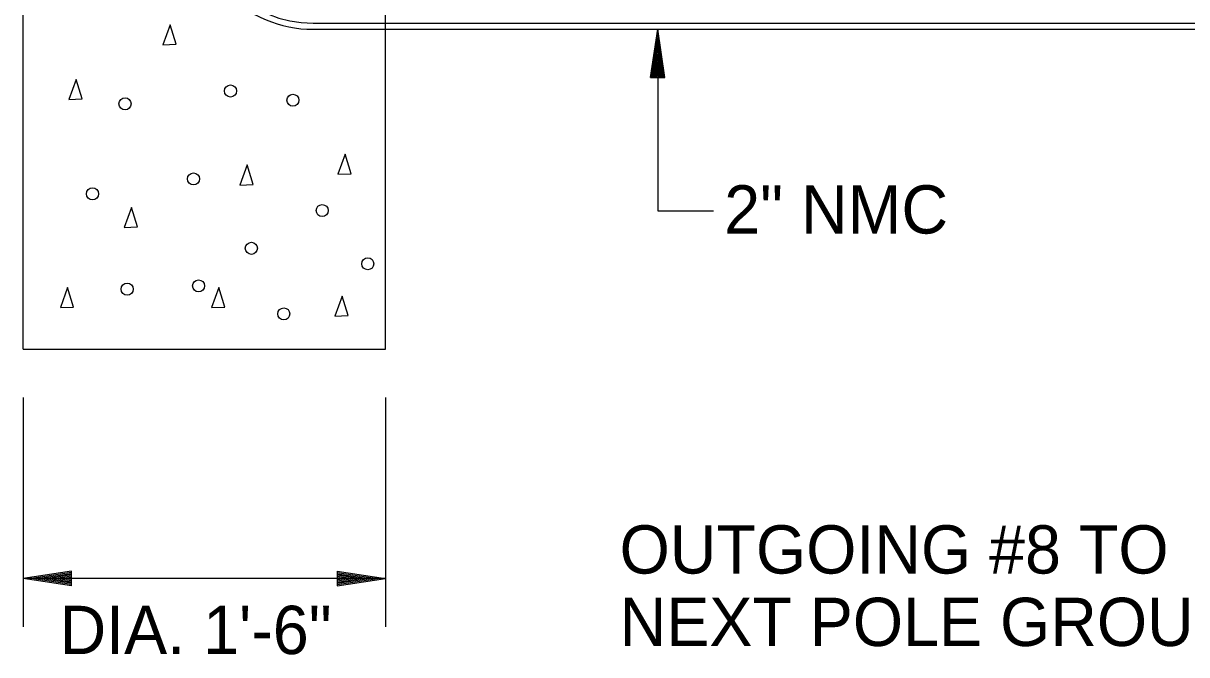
# Model space of a CAD drawing. Extents: x 1695551 to 1695718, y 544410 to 544516.
# Drawn here: x 1695569.87 to 1695587.94, y 544471.5 to 544481.31 of the extents above; entities that cross this region are included whole.
import ezdxf

# ---------------------------------------------------------------- set-up
doc = ezdxf.new("R2010")
doc.units = 0
doc.layers.add('R_Draft', color=7, linetype='Continuous')

msp = doc.modelspace()

# ---------------------------------------------------------------- linework, layer by layer
at = {"layer": 'R_Draft'}
for p, q in [((1695569.874, 544476.251), (1695569.874, 544487.501)), ((1695575.499, 544476.251), (1695575.499, 544487.501)), ((1695574.374, 544481.311), (1695592.925, 544481.311)), ((1695574.374, 544481.217), (1695592.925, 544481.217)), ((1695579.615, 544480.467), (1695579.727, 544481.217)), ((1695579.727, 544481.217), (1695579.727, 544478.399)), ((1695579.84, 544480.467), (1695579.727, 544481.217)), ((1695579.633, 544480.467), (1695579.727, 544481.092)), ((1695579.821, 544480.467), (1695579.727, 544481.092)), ((1695579.653, 544480.467), (1695579.727, 544480.963)), ((1695579.671, 544480.467), (1695579.727, 544480.838)), ((1695579.802, 544480.467), (1695579.727, 544480.963)), ((1695579.783, 544480.467), (1695579.727, 544480.838)), ((1695579.691, 544480.467), (1695579.727, 544480.711)), ((1695579.764, 544480.467), (1695579.727, 544480.711)), ((1695579.615, 544480.467), (1695579.84, 544480.467)), ((1695579.71, 544480.467), (1695579.727, 544480.585)), ((1695579.745, 544480.467), (1695579.727, 544480.585)), ((1695579.727, 544478.399), (1695580.591, 544478.399)), ((1695569.874, 544476.251), (1695575.499, 544476.251)), ((1695569.874, 544475.501), (1695569.874, 544471.939)), ((1695575.499, 544475.501), (1695575.499, 544471.939)), ((1695570.624, 544472.801), (1695569.874, 544472.689)), ((1695575.499, 544472.689), (1695569.874, 544472.689)), ((1695570.624, 544472.576), (1695569.874, 544472.689)), ((1695570.624, 544472.783), (1695569.999, 544472.689)), ((1695570.624, 544472.595), (1695569.999, 544472.689)), ((1695570.624, 544472.763), (1695570.128, 544472.689)), ((1695570.624, 544472.614), (1695570.128, 544472.689)), ((1695570.624, 544472.745), (1695570.253, 544472.689)), ((1695570.624, 544472.633), (1695570.253, 544472.689)), ((1695570.624, 544472.726), (1695570.38, 544472.689)), ((1695570.624, 544472.652), (1695570.38, 544472.689)), ((1695570.624, 544472.706), (1695570.505, 544472.689)), ((1695570.624, 544472.671), (1695570.505, 544472.689)), ((1695570.624, 544472.576), (1695570.624, 544472.801)), ((1695574.749, 544472.801), (1695575.499, 544472.689)), ((1695574.749, 544472.801), (1695574.749, 544472.576)), ((1695574.749, 544472.783), (1695575.373, 544472.689)), ((1695574.749, 544472.763), (1695575.244, 544472.689)), ((1695574.749, 544472.745), (1695575.12, 544472.689)), ((1695574.749, 544472.725), (1695574.992, 544472.689)), ((1695574.749, 544472.706), (1695574.867, 544472.689)), ((1695574.749, 544472.576), (1695575.499, 544472.689)), ((1695574.749, 544472.652), (1695574.992, 544472.689)), ((1695574.749, 544472.614), (1695575.244, 544472.689)), ((1695574.749, 544472.595), (1695575.373, 544472.689)), ((1695574.749, 544472.633), (1695575.12, 544472.689)), ((1695574.749, 544472.671), (1695574.867, 544472.689))]:
    msp.add_line(p, q, dxfattribs=at)
for points in [[(1695572.156, 544481.287), (1695572.043, 544480.975), (1695572.249, 544480.984), (1695572.156, 544481.287)], [(1695570.695, 544480.44), (1695570.582, 544480.129), (1695570.788, 544480.137), (1695570.695, 544480.44)], [(1695574.873, 544479.278), (1695574.76, 544478.967), (1695574.966, 544478.975), (1695574.873, 544479.278)], [(1695573.353, 544479.111), (1695573.239, 544478.799), (1695573.445, 544478.808), (1695573.353, 544479.111)], [(1695571.557, 544478.452), (1695571.443, 544478.141), (1695571.65, 544478.149), (1695571.557, 544478.452)], [(1695570.563, 544477.206), (1695570.45, 544476.895), (1695570.656, 544476.903), (1695570.563, 544477.206)], [(1695572.91, 544477.206), (1695572.796, 544476.895), (1695573.003, 544476.903), (1695572.91, 544477.206)], [(1695574.825, 544477.074), (1695574.712, 544476.763), (1695574.918, 544476.772), (1695574.825, 544477.074)]]:
    msp.add_lwpolyline(points, dxfattribs=at)
for centre in [(1695573.093, 544480.259), (1695571.454, 544480.059), (1695574.062, 544480.115), (1695572.518, 544478.893), (1695570.948, 544478.662), (1695574.517, 544478.402), (1695573.416, 544477.816), (1695575.224, 544477.576), (1695571.488, 544477.181), (1695572.597, 544477.232), (1695573.919, 544476.797)]:
    msp.add_circle(centre, 0.0937, dxfattribs=at)
for radius in [1.875, 1.781]:
    msp.add_arc((1695574.374, 544483.092), radius, 180, 270, dxfattribs=at)

# ---------------------------------------------------------------- texts
for s, p in [('2" NMC', (1695580.76, 544478.045)), ('OUTGOING #8 TO', (1695579.135, 544472.765)), ('NEXT POLE GROUND', (1695579.135, 544471.64)), ('DIA. 1\'-6"', (1695570.437, 544471.515))]:
    msp.add_text(s, height=0.75, dxfattribs=at).set_placement(p)

doc.saveas('drawing.dxf')
